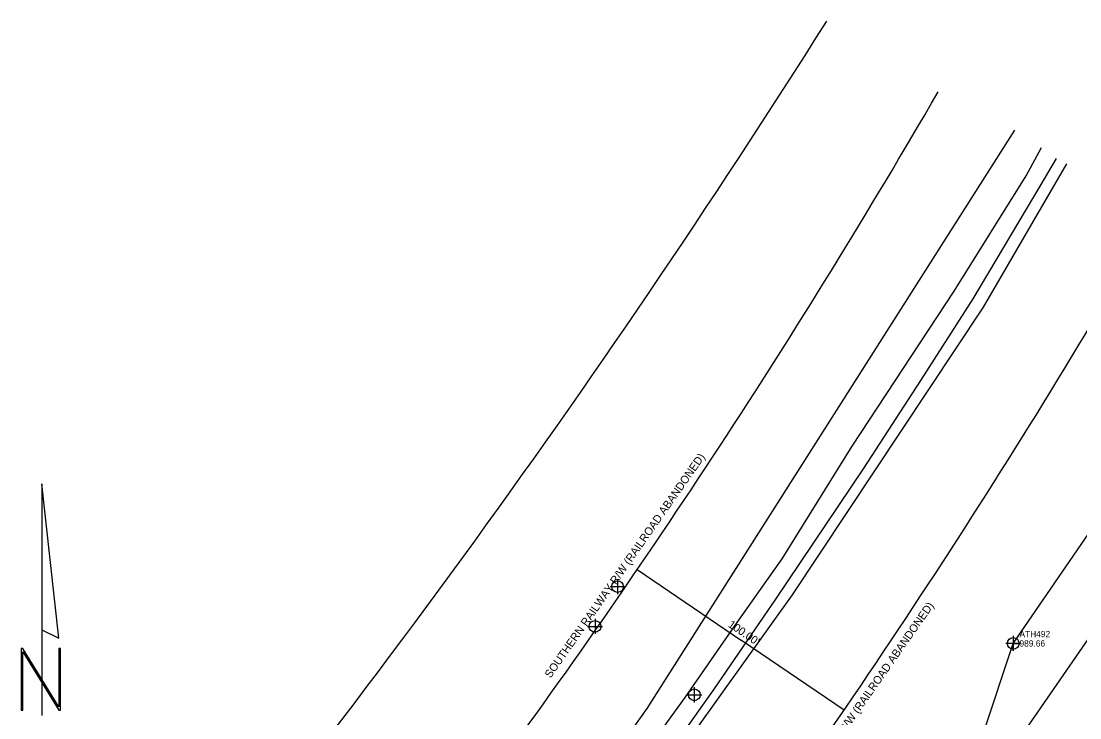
# Model space of a CAD drawing. Extents: x 1116345 to 1117546, y 660629 to 661859.
# Drawn here: x 1116811.4 to 1117234.8, y 661580.4 to 661858.9 of the extents above; entities that cross this region are included whole.
import ezdxf

# ---------------------------------------------------------------- set-up
doc = ezdxf.new("R2010")
doc.units = 0
for name, color, linetype in [('Cogo Default Point CELL', 7, 'Continuous'), ('CTL North Arrow NAD 83 NA 2011 CELL', 7, 'Continuous'), ('Exist DTM Drainline Cogo Elevation', 7, 'Continuous'), ('Exist DTM Drainline Cogo Number', 7, 'Continuous'), ('Exist DTM Drainline Cogo Point CELL', 7, 'Continuous'), ('Exist Hydro Jurisdictional Stream or Body of Water', 7, 'Continuous'), ('Exist Right of Way Line', 7, 'Continuous'), ('Exist Right of Way Line Text', 7, 'Continuous'), ('Exist Roads EOP', 7, 'Continuous'), ('Exist Roads Soil', 7, 'Continuous'), ('Exist Vegetation Woods Line', 7, 'Continuous')]:
    doc.layers.add(name, color=color, linetype=linetype)

msp = doc.modelspace()

# ---------------------------------------------------------------- linework, layer by layer
at = {"layer": 'Cogo Default Point CELL'}
for points in [[(1117049.89, 661635.87), (1117049.89, 661632.87)], [(1117046.89, 661632.87), (1117049.89, 661632.87)], [(1117049.89, 661632.87), (1117052.89, 661632.87)], [(1117049.89, 661632.87), (1117049.89, 661629.87)], [(1117037.88, 661616.95), (1117040.88, 661616.95)], [(1117040.88, 661619.95), (1117040.88, 661616.95)], [(1117040.88, 661616.95), (1117043.88, 661616.95)], [(1117040.88, 661616.95), (1117040.88, 661613.95)], [(1117080.6, 661592.6), (1117080.6, 661589.6)], [(1117077.6, 661589.6), (1117080.6, 661589.6)], [(1117080.6, 661589.6), (1117083.6, 661589.6)], [(1117080.6, 661589.6), (1117080.6, 661586.6)]]:
    msp.add_lwpolyline(points, dxfattribs=at)
for centre in [(1117049.89, 661632.87), (1117040.88, 661616.95), (1117080.6, 661589.6)]:
    msp.add_circle(centre, 2.34, dxfattribs=at)
at = {"layer": 'CTL North Arrow NAD 83 NA 2011 CELL'}
msp.add_line((1116819.75, 661586.69), (1116819.75, 661586.69), dxfattribs=at)
for points in [[(1116819.6, 661673.97), (1116819.6, 661615.65), (1116826.47, 661612.21)], [(1116811.37, 661583.42), (1116812.06, 661583.42), (1116812.06, 661606.75), (1116826.47, 661583.42), (1116827.16, 661583.42), (1116827.16, 661608.11), (1116826.47, 661608.11), (1116826.47, 661584.79), (1116812.06, 661608.11), (1116811.37, 661608.11)]]:
    msp.add_lwpolyline(points, close=True, dxfattribs=at)
msp.add_lwpolyline([(1116819.6, 661615.65), (1116819.6, 661581.35)], dxfattribs=at)
at = {"layer": 'Exist DTM Drainline Cogo Point CELL'}
msp.add_lwpolyline([(1117208.15, 661613.15), (1117208.15, 661607.15), (1117208.15, 661610.15), (1117211.15, 661610.15), (1117205.15, 661610.15)], dxfattribs=at)
msp.add_circle((1117208.15, 661610.15), 2.34, dxfattribs=at)
at = {"layer": 'Exist Hydro Jurisdictional Stream or Body of Water'}
msp.add_lwpolyline([(1117125.36, 661468.03), (1117140.15, 661498.02), (1117164.52, 661530.7), (1117196.25, 661574.43), (1117208.15, 661610.15), (1117250.57, 661671.87), (1117271.1, 661697.99)], dxfattribs=at)
at = {"layer": 'Exist Right of Way Line'}
for centre, radius, start, end in [((1113861.12, 663924.32), 3869.72, 320.06667, 327.74218), ((1114555.87, 663349.35), 3030.27, 323.62772, 329.92248), ((1114555.87, 663349.35), 3130.27, 323.60349, 329.92248)]:
    msp.add_arc(centre, radius, start, end, dxfattribs=at)
at = {"layer": 'Exist Right of Way Line Text'}
for p in [(1117057.78, 661639.68), (1117140.48, 661583.47)]:
    msp.add_line(p, (1117099.42, 661611.37), dxfattribs=at)
at = {"layer": 'Exist Roads EOP'}
msp.add_spline([(1117102.29, 661387.33), (1117126.62, 661394.06), (1117156.42, 661404.98), (1117187.2, 661421.69), (1117219.89, 661448.41), (1117247.01, 661480.82), (1117275.55, 661531.18), (1117296.66, 661577.27), (1117320.8, 661635.68)], degree=3, dxfattribs=at)
at = {"layer": 'Exist Roads Soil'}
for points in [[(1116964.44, 661438.72), (1116986.86, 661464.48), (1117002.48, 661483.48), (1117033.75, 661528.36), (1117059.44, 661564.38), (1117076.95, 661588.51), (1117096.75, 661617.23), (1117115.73, 661643.92), (1117143.77, 661689), (1117184.56, 661750.96), (1117213.34, 661797.09), (1117219.45, 661808.47)], [(1117225.38, 661804.01), (1117219.15, 661793.59), (1117192.04, 661747.99), (1117171.01, 661715.33), (1117148.14, 661680), (1117113.02, 661627.81), (1117088.44, 661591.81), (1117057.75, 661548.54), (1117030.7, 661510.69), (1117010.61, 661482.09), (1116975.46, 661437.79)]]:
    msp.add_lwpolyline(points, dxfattribs=at)
at = {"layer": 'Exist Vegetation Woods Line'}
for points in [[(1117208.66, 661815.33), (1117061.61, 661584.19), (1116958.01, 661438.28)], [(1116989.01, 661444.95), (1117071.18, 661561.57), (1117119.82, 661629.61), (1117196.26, 661744.55), (1117229.54, 661801.86)], [(1117331.77, 661706.88), (1117284.76, 661578.38), (1117241.02, 661497.84), (1117170.97, 661427.76), (1117121.7, 661414.67), (1117133.58, 661458.9), (1117169.21, 661515.67), (1117206.6, 661566.28), (1117265.11, 661650.77), (1117285.78, 661686.42), (1117290.62, 661714.15)]]:
    msp.add_lwpolyline(points, dxfattribs=at)

# ---------------------------------------------------------------- texts
at = {"layer": 'Exist DTM Drainline Cogo Elevation'}
msp.add_text('989.66', height=2.5, dxfattribs=at).set_placement((1117210.65, 661608.9))
at = {"layer": 'Exist DTM Drainline Cogo Number'}
msp.add_text('ATH492', height=2.5, dxfattribs=at).set_placement((1117210.65, 661612.65))
at = {"layer": 'Exist Right of Way Line Text'}
for s, rotation, p in [('SOUTHERN RAILWAY R/W (RAILROAD ABANDONED)', 55.0555, (1117023.1, 661596.06)), ('SOUTHERN RAILWAY R/W (RAILROAD ABANDONED)', 55.0555, (1117114.63, 661536.62)), ("100.00'", 325.7967, (1117093.82, 661617.03))]:
    msp.add_text(s, height=3.2, rotation=rotation, dxfattribs=at).set_placement(p)

doc.saveas('drawing.dxf')
